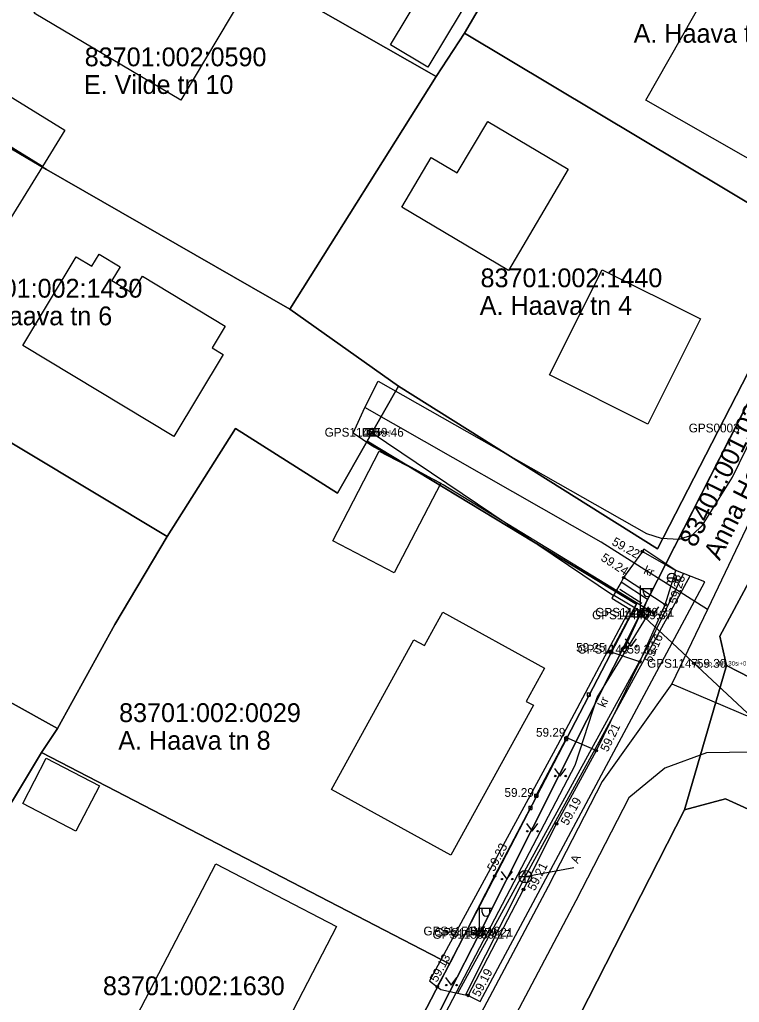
# Model space of a CAD drawing. Extents: x 580119 to 583377, y 6518915 to 6520820.
# Drawn here: x 581802.2 to 581859.6, y 6520069.8 to 6520148.1 of the extents above; entities that cross this region are included whole.
import ezdxf

# ---------------------------------------------------------------- set-up
doc = ezdxf.new("R2010")
doc.units = 0
for name, color, linetype in [('AED', 7, 'Continuous'), ('ELRAJATISMP', 7, 'Continuous'), ('HALJASTUS', 7, 'Continuous'), ('Hoone Elu- või ühiskondlik hoone', 7, 'Continuous'), ('Hoone Kõrval- või tootmishoone', 7, 'Continuous'), ('Hoone Vundament', 7, 'Continuous'), ('KKAEV', 7, 'Continuous'), ('KORGUS-EH2000', 7, 'Continuous'), ('KTRASS', 7, 'Continuous'), ('L_AADRESS', 7, 'Continuous'), ('MAAMUDEL', 7, 'Continuous'), ('MOOTKORG-EH2000', 7, 'Continuous'), ('MOOTMPUNKT', 7, 'Continuous'), ('MOOTNR', 7, 'Continuous'), ('MOOTPIIR', 7, 'Continuous'), ('MPOHULIIN', 7, 'Continuous'), ('PIIR', 7, 'Continuous'), ('POST', 7, 'Continuous'), ('Rippe kõrgus', 7, 'Continuous'), ('SIOHULIIN', 7, 'Continuous'), ('TEE', 7, 'Continuous'), ('Tee Liiklusala', 7, 'Continuous'), ('Tee Tänav Kruuskate', 7, 'Continuous'), ('Tee Tänav Püsikate', 7, 'Continuous'), ('TUNNUS', 7, 'Continuous'), ('VKAEV', 7, 'Continuous'), ('VTRASS', 7, 'Continuous')]:
    doc.layers.add(name, color=color, linetype=linetype)

msp = doc.modelspace()

# ---------------------------------------------------------------- linework, layer by layer
at = {"layer": 'AED'}
for p, q in [((581849.358, 6520097.716), (581851.334, 6520101.433)), ((581849.233, 6520097.841), (581849.233, 6520097.591)), ((581849.233, 6520097.841), (581849.483, 6520097.841)), ((581849.233, 6520097.591), (581849.483, 6520097.591)), ((581849.483, 6520097.841), (581849.483, 6520097.591)), ((581847.447, 6520094.431), (581847.447, 6520094.181)), ((581847.447, 6520094.431), (581847.697, 6520094.431)), ((581847.447, 6520094.181), (581847.697, 6520094.181)), ((581847.697, 6520094.431), (581847.697, 6520094.181)), ((581843.392, 6520086.248), (581845.776, 6520090.772)), ((581845.651, 6520090.897), (581845.651, 6520090.647)), ((581845.651, 6520090.897), (581845.901, 6520090.897)), ((581845.651, 6520090.647), (581845.901, 6520090.647)), ((581845.901, 6520090.897), (581845.901, 6520090.647)), ((581843.267, 6520086.373), (581843.267, 6520086.123)), ((581843.267, 6520086.373), (581843.517, 6520086.373)), ((581843.517, 6520086.373), (581843.517, 6520086.123)), ((581843.267, 6520086.123), (581843.517, 6520086.123)), ((581842.798, 6520085.401), (581842.798, 6520085.151)), ((581842.798, 6520085.401), (581843.048, 6520085.401)), ((581842.798, 6520085.151), (581843.048, 6520085.151)), ((581843.048, 6520085.401), (581843.048, 6520085.151))]:
    msp.add_line(p, q, dxfattribs=at)
msp.add_lwpolyline([(581835.497, 6520071.002), (581836.568, 6520072.987), (581840.076, 6520079.831), (581842.923, 6520085.276)], dxfattribs=at)
at = {"layer": 'ELRAJATISMP'}
for p, q in [((581830.086, 6520115.519), (581830.086, 6520114.922)), ((581830.358, 6520115.519), (581830.358, 6520114.922)), ((581851.586, 6520101.061), (581851.586, 6520100.464)), ((581851.857, 6520101.061), (581851.857, 6520100.464))]:
    msp.add_line(p, q, dxfattribs=at)
for points in [[(581829.625, 6520115.519), (581830.819, 6520115.519), (581830.819, 6520114.922), (581829.625, 6520114.922)], [(581851.124, 6520101.061), (581852.319, 6520101.061), (581852.319, 6520100.464), (581851.124, 6520100.464)]]:
    msp.add_lwpolyline(points, close=True, dxfattribs=at)
at = {"layer": 'HALJASTUS'}
for p, q in [((581851.818, 6520101.572), (581850.061, 6520102.69)), ((581852.272, 6520101.297), (581852.735, 6520100.69)), ((581852.735, 6520100.69), (581853.181, 6520101.297)), ((581850.491, 6520098.745), (581850.954, 6520098.138)), ((581850.954, 6520098.138), (581851.4, 6520098.745)), ((581844.852, 6520088.418), (581845.315, 6520087.811)), ((581845.315, 6520087.811), (581845.761, 6520088.418)), ((581842.616, 6520084.013), (581843.08, 6520083.406)), ((581843.08, 6520083.406), (581843.525, 6520084.013)), ((581840.59, 6520080.203), (581841.054, 6520079.596)), ((581841.054, 6520079.596), (581841.499, 6520080.203)), ((581838.39, 6520075.799), (581838.853, 6520075.192)), ((581838.853, 6520075.192), (581839.299, 6520075.799)), ((581836.154, 6520071.744), (581836.618, 6520071.137)), ((581836.618, 6520071.137), (581837.063, 6520071.744))]:
    msp.add_line(p, q, dxfattribs=at)
msp.add_lwpolyline([(581849.642, 6520102.211), (581851.868, 6520100.864), (581852.266, 6520101.891), (581850.159, 6520103.272)], dxfattribs=at)
for centre in [(581852.334, 6520100.69), (581853.163, 6520100.69), (581850.553, 6520098.138), (581851.382, 6520098.138), (581844.914, 6520087.811), (581845.743, 6520087.811), (581842.679, 6520083.406), (581843.507, 6520083.406), (581840.653, 6520079.596), (581841.481, 6520079.596), (581838.452, 6520075.192), (581839.281, 6520075.192), (581836.217, 6520071.137), (581837.045, 6520071.137)]:
    msp.add_circle(centre, 0.055, dxfattribs=at)
at = {"layer": 'Hoone Elu- või ühiskondlik hoone'}
for points in [[(581820.033, 6520150.116), (581815.051, 6520141.712), (581803.344, 6520148.653), (581808.326, 6520157.057)], [(581852.13, 6520141.691), (581859.68, 6520154.991), (581868.781, 6520149.822), (581865.61, 6520144.241), (581867.15, 6520143.372), (581862.77, 6520135.652)], [(581808.51, 6520129.427), (581810.185, 6520128.419), (581809.526, 6520127.321), (581811.166, 6520126.336), (581811.973, 6520127.674), (581818.588, 6520123.693), (581817.547, 6520121.957), (581818.418, 6520121.435), (581814.469, 6520114.888), (581802.432, 6520122.134), (581806.694, 6520129.217), (581807.935, 6520128.473)], [(581856.487, 6520124.265), (581852.294, 6520115.878), (581844.456, 6520119.798), (581848.65, 6520128.184)], [(581843.178, 6520093.45), (581836.591, 6520081.493), (581827.059, 6520086.744), (581833.636, 6520098.683), (581834.479, 6520098.219), (581835.94, 6520100.872), (581844.04, 6520096.41), (581842.578, 6520093.757)], [(581825.267, 6520068.487), (581821.358, 6520060.968), (581810.468, 6520066.639), (581817.832, 6520080.816), (581827.456, 6520075.811), (581824.001, 6520069.151)]]:
    msp.add_lwpolyline(points, close=True, dxfattribs=at)
at = {"layer": 'Hoone Kõrval- või tootmishoone'}
for points in [[(581837.404, 6520148.761), (581834.753, 6520144.334), (581831.776, 6520146.116), (581834.427, 6520150.544)], [(581803.994, 6520136.423), (581796.95, 6520140.751), (581798.728, 6520143.644), (581805.772, 6520139.316)], [(581796.95, 6520140.751), (581803.994, 6520136.423), (581800.922, 6520131.425), (581795.455, 6520134.786), (581794.09, 6520132.566), (581789.097, 6520135.635), (581792.803, 6520141.666), (581796.221, 6520139.565)], [(581832.67, 6520133.172), (581835.02, 6520137.132), (581837.09, 6520135.912), (581839.52, 6520140.002), (581845.95, 6520136.191), (581841.17, 6520128.132)], [(581804.301, 6520089.226), (581808.544, 6520087.024), (581806.669, 6520083.412), (581802.426, 6520085.614)]]:
    msp.add_lwpolyline(points, close=True, dxfattribs=at)
at = {"layer": 'Hoone Vundament'}
msp.add_lwpolyline([(581830.867, 6520113.723), (581835.778, 6520111.172), (581832.066, 6520104.025), (581827.155, 6520106.576)], close=True, dxfattribs=at)
at = {"layer": 'KKAEV'}
for p, q in [((581842.519, 6520079.285), (581842.519, 6520080.285)), ((581842.019, 6520079.785), (581843.019, 6520079.785))]:
    msp.add_line(p, q, dxfattribs=at)
msp.add_circle((581842.519, 6520079.785), 0.5, dxfattribs=at)
at = {"layer": 'KORGUS-EH2000'}
for centre in [(581851.862, 6520105.711), (581850.367, 6520103.628), (581853.692, 6520101.469), (581849.218, 6520097.728), (581851.671, 6520096.92), (581845.807, 6520090.875), (581848.191, 6520089.836), (581843.392, 6520086.248), (581845.018, 6520084.001), (581840.076, 6520079.831), (581842.377, 6520078.763), (581835.497, 6520071.002), (581837.958, 6520070.314)]:
    msp.add_circle(centre, 0.1, dxfattribs=at)
at = {"layer": 'KTRASS'}
msp.add_line((581842.519, 6520079.785), (581846.392, 6520080.516), dxfattribs=at)
msp.add_lwpolyline([(581855.638, 6520103.758), (581842.519, 6520079.785), (581837.745, 6520070.359)], dxfattribs=at)
at = {"layer": 'MOOTMPUNKT'}
for centre in [(581830.222, 6520115.22), (581859.481, 6520115.561), (581855.953, 6520096.795)]:
    msp.add_circle(centre, 0.1, dxfattribs=at)
at = {"layer": 'MOOTPIIR'}
msp.add_lwpolyline([(581834.886, 6520071.472), (581835.497, 6520071.002), (581835.795, 6520070.775), (581837.958, 6520070.314), (581838.912, 6520069.817), (581856.835, 6520103.284), (581854.528, 6520104.199), (581851.988, 6520105.899), (581851.862, 6520105.711), (581850.367, 6520103.628), (581850.159, 6520103.272), (581849.433, 6520101.984), (581850.871, 6520101.105), (581845.086, 6520090.262)], close=True, dxfattribs=at)
at = {"layer": 'MPOHULIIN'}
for p, q in [((581864.425, 6520125.702), (581853.741, 6520104.726)), ((581830.222, 6520115.22), (581849.563, 6520102.214)), ((581853.741, 6520104.726), (581851.721, 6520100.762)), ((581837.895, 6520075.45), (581838.86, 6520075.263))]:
    msp.add_line(p, q, dxfattribs=at)
for points in [[(581851.721, 6520100.762), (581838.86, 6520075.263), (581836.498, 6520070.625)], [(581851.721, 6520100.762), (581854.232, 6520098.424)], [(581854.232, 6520098.424), (581869.033, 6520084.64), (581898.232, 6520068.443), (581929.764, 6520051.169), (581964.377, 6520031.774), (581989.598, 6520017.96), (582014.996, 6520004.053), (582041.548, 6519986.36), (582056.944, 6519974.839)], [(581836.498, 6520070.625), (581821.164, 6520040.517)]]:
    msp.add_lwpolyline(points, dxfattribs=at)
at = {"layer": 'PIIR'}
for points in [[(581818.25, 6520012.64), (581808.31, 6520018.92), (581824.83, 6520050.4), (581836.47, 6520072.82), (581851.4, 6520101.52), (581829.9, 6520114.5), (581832.4, 6520118.89), (581853.07, 6520105.93), (581865.62, 6520130.32), (581875.62, 6520150.43), (581897.71, 6520194.09), (581905.22, 6520189.53), (581889.06, 6520159.5), (581879.18, 6520139.97), (581876.38, 6520134.67), (581873.75, 6520129.28), (581870.97, 6520123.99), (581868.38, 6520118.69), (581865.54, 6520113.3), (581862.86, 6520107.92), (581858.03, 6520098.95), (581858.58, 6520096.63), (581855.23, 6520085.11)], [(581812.15, 6520182.64), (581846.68, 6520162.43), (581837.68, 6520147.06), (581835.4, 6520143.6), (581800.99, 6520163.2)], [(581846.68, 6520162.43), (581848.92, 6520166.07), (581875.62, 6520150.43), (581865.62, 6520130.32), (581837.68, 6520147.06)], [(581790.11, 6520144.42), (581800.99, 6520163.2), (581835.4, 6520143.6), (581823.73, 6520125.03), (581804.32, 6520136.18), (581798.27, 6520139.74)], [(581823.73, 6520125.03), (581835.4, 6520143.6), (581837.68, 6520147.06), (581865.62, 6520130.32), (581853.07, 6520105.93), (581832.4, 6520118.89)], [(581790.11, 6520144.42), (581798.27, 6520139.74), (581804.32, 6520136.18), (581823.73, 6520125.03), (581832.4, 6520118.89), (581829.9, 6520114.5), (581827.55, 6520110.37), (581819.41, 6520115.52), (581813.96, 6520106.91), (581779.28, 6520127.73)], [(581779.28, 6520127.73), (581813.96, 6520106.91), (581809.78, 6520099.89), (581805.2, 6520091.6), (581786.76, 6520101.83), (581782.86, 6520103.86), (581769.84, 6520111.32)], [(581819.41, 6520115.52), (581827.55, 6520110.37), (581829.9, 6520114.5), (581851.4, 6520101.52), (581836.47, 6520072.82), (581803.92, 6520089.68), (581805.2, 6520091.6), (581809.78, 6520099.89), (581813.96, 6520106.91)], [(581768.1, 6520101.82), (581765.39, 6520103.31), (581769.84, 6520111.32), (581782.86, 6520103.86), (581786.76, 6520101.83), (581805.2, 6520091.6), (581803.92, 6520089.68), (581794.38, 6520073.84), (581789.29, 6520076.96), (581762.75, 6520093.2)], [(581858.58, 6520096.63), (581858.03, 6520098.95), (581862.86, 6520107.92), (581873.01, 6520102.73), (581883.66, 6520097.35), (581908.93, 6520084.35), (581904.4, 6520076.28), (581886.27, 6520086), (581879.26, 6520086)], [(581792.34, 6520070.46), (581794.38, 6520073.84), (581803.92, 6520089.68), (581836.47, 6520072.82), (581824.83, 6520050.4), (581803.43, 6520063.65)], [(581888.28, 6520072.43), (581876.44, 6520050.07), (581847.29, 6519995.61), (581818.25, 6520012.64), (581855.23, 6520085.11), (581858.5, 6520085.99)]]:
    msp.add_lwpolyline(points, close=True, dxfattribs=at)
msp.add_lwpolyline([(581949.86, 6520009.55), (581943.51, 6520012.98), (581956.4, 6520035.78), (581930.04, 6520050.18), (581888.28, 6520072.43), (581858.5, 6520085.99), (581855.23, 6520085.11), (581858.58, 6520096.63), (581879.26, 6520086), (581886.27, 6520086), (581904.4, 6520076.28), (581908.93, 6520084.35), (581911.76, 6520089.61), (581914.75, 6520094.85), (581917.61, 6520100.1), (581919.2, 6520103.01), (581923.71, 6520100.64), (581925.66, 6520099.62), (581920.7, 6520095.82), (581908.98, 6520073.94), (581935.27, 6520059.68), (581961.38, 6520044.71)], dxfattribs=at)
at = {"layer": 'POST'}
for p, q in [((581851.721, 6520101.012), (581851.721, 6520103.012)), ((581851.721, 6520102.762), (581852.721, 6520102.762)), ((581851.948, 6520102.441), (581851.948, 6520102.762)), ((581852.561, 6520102.441), (581852.561, 6520102.762)), ((581851.721, 6520100.762), (581851.721, 6520100.762)), ((581838.86, 6520075.513), (581838.86, 6520077.513)), ((581838.86, 6520077.263), (581839.86, 6520077.263)), ((581839.087, 6520076.942), (581839.087, 6520077.263)), ((581839.7, 6520076.942), (581839.7, 6520077.263)), ((581838.86, 6520075.263), (581838.86, 6520075.263))]:
    msp.add_line(p, q, dxfattribs=at)
msp.add_lwpolyline([(581851.721, 6520100.762), (581850.402, 6520097.925)], dxfattribs=at)
for centre, radius in [((581830.222, 6520115.22), 0.25), ((581851.721, 6520100.762), 0.25), ((581850.402, 6520097.925), 0.2), ((581838.86, 6520075.263), 0.25)]:
    msp.add_circle(centre, radius, dxfattribs=at)
for centre in [(581852.255, 6520102.441), (581839.393, 6520076.942)]:
    msp.add_arc(centre, 0.306, 180, 0, dxfattribs=at)
at = {"layer": 'SIOHULIIN'}
for points in [[(581853.741, 6520104.726), (581864.425, 6520125.702)], [(581854.232, 6520098.424), (581851.721, 6520100.762), (581853.741, 6520104.726)], [(581836.498, 6520070.625), (581838.86, 6520075.263), (581851.721, 6520100.762)], [(581869.033, 6520084.64), (581854.232, 6520098.424)], [(581808.669, 6520016.764), (581821.164, 6520040.517), (581836.498, 6520070.625)]]:
    msp.add_lwpolyline(points, dxfattribs=at)
at = {"layer": 'TEE'}
for points in [[(581851.862, 6520105.711), (581854.528, 6520104.199)], [(581837.958, 6520070.314), (581842.377, 6520078.763), (581845.018, 6520084.001), (581848.191, 6520089.836), (581851.671, 6520096.92), (581853.692, 6520101.469), (581854.528, 6520104.199)], [(581853.692, 6520101.469), (581850.367, 6520103.628)], [(581851.671, 6520096.92), (581849.218, 6520097.728)], [(581845.807, 6520090.875), (581848.191, 6520089.836)]]:
    msp.add_lwpolyline(points, dxfattribs=at)
at = {"layer": 'Tee Liiklusala'}
for points in [[(581742.215, 6520054.723), (581805.663, 6520015.653), (581807.918, 6520015.737), (581809.742, 6520016.857), (581827.568, 6520051.921), (581835.83, 6520068.282), (581846.508, 6520088.672), (581848.263, 6520094.065), (581852.483, 6520100.961), (581835.959, 6520111.027), (581830.266, 6520114.149), (581828.794, 6520115.158), (581829.718, 6520117.195), (581830.788, 6520119.284), (581852.184, 6520107.138), (581853.36, 6520106.77), (581854.804, 6520106.704), (581855.859, 6520107.038), (581856.65, 6520107.81), (581859.04, 6520111.64), (581881.29, 6520157.17)], [(581951.622, 6520039.928), (581930.601, 6520052.21), (581908.83, 6520065.921), (581904.459, 6520069.499), (581880.476, 6520080.917), (581860.654, 6520089.709), (581856.965, 6520089.651), (581853.653, 6520088.441), (581850.79, 6520086.066), (581846.566, 6520077.855), (581840.27, 6520065.98), (581832.895, 6520051.299), (581814.422, 6520014.831), (581814.487, 6520011.909), (581816.356, 6520009.507), (581833.173, 6519999.999), (581968.761, 6519918.78)]]:
    msp.add_lwpolyline(points, dxfattribs=at)
at = {"layer": 'Tee Tänav Kruuskate'}
msp.add_lwpolyline([(581857.05, 6520101.082), (581848.58, 6520106.462), (581829.718, 6520117.195)], dxfattribs=at)
at = {"layer": 'Tee Tänav Püsikate'}
for points in [[(581904.384, 6520197.949), (581891.674, 6520171.939), (581884.02, 6520156.581), (581876.34, 6520141.461), (581857.05, 6520101.082)], [(581857.05, 6520101.082), (581854.2, 6520095.172)], [(581854.2, 6520095.172), (581848.649, 6520087.369), (581844.35, 6520079.012), (581838.05, 6520067.131), (581809.38, 6520010.542)], [(581854.2, 6520095.172), (581861.65, 6520092.002), (581881.49, 6520083.202), (581905.64, 6520071.702)]]:
    msp.add_lwpolyline(points, dxfattribs=at)
at = {"layer": 'VKAEV'}
for p, q in [((581853.854, 6520103.627), (581854.554, 6520103.627)), ((581853.957, 6520103.38), (581853.817, 6520103.24)), ((581854.451, 6520103.38), (581854.591, 6520103.24))]:
    msp.add_line(p, q, dxfattribs=at)
msp.add_circle((581854.204, 6520103.627), 0.35, dxfattribs=at)
at = {"layer": 'VTRASS'}
msp.add_line((581854.204, 6520103.627), (581854.832, 6520103.318), dxfattribs=at)
msp.add_lwpolyline([(581837.138, 6520070.489), (581851.933, 6520097.485), (581852.507, 6520098.532), (581855.141, 6520103.956)], dxfattribs=at)

# ---------------------------------------------------------------- texts
at = {"layer": 'KORGUS-EH2000'}
for s, rotation, p in [(' 59.22', 330.44083, (581849.138, 6520106.415)), (' 59.24', 327.00431, (581848.271, 6520105.185)), (' 59.28', 72.96455, (581854.528, 6520101.213)), (' 59.16', 66.05189, (581852.471, 6520096.565)), (' 59.21', 63.83848, (581848.977, 6520089.45)), (' 59.19', 61.45736, (581845.786, 6520083.583)), (' 59.23', 62.40186, (581839.921, 6520079.912)), (' 59.21', 63.24539, (581843.158, 6520078.369)), (' 59.13', 61.65057, (581835.343, 6520071.085)), (' 59.19', 62.3903, (581838.733, 6520069.908))]:
    msp.add_text(s, height=0.7, rotation=rotation, dxfattribs=at).set_placement(p)
for s, p in [(' 59.25', (581846.314, 6520097.715)), (' 59.29', (581843.116, 6520090.944)), (' 59.29', (581840.6, 6520086.146))]:
    msp.add_text(s, height=0.7, dxfattribs=at).set_placement(p)
at = {"layer": 'L_AADRESS'}
for s, p in [('A. Haava tn 4a', (581851.163, 6520146.282)), ('E. Vilde tn 10', (581807.305, 6520142.202)), ('A. Haava tn 4', (581838.888, 6520124.582)), ('A. Haava tn 6', (581797.409, 6520123.752)), ('A. Haava tn 8', (581810.048, 6520089.907))]:
    msp.add_text(s, height=1.5, dxfattribs=at).set_placement(p)
msp.add_text('Anna Haava tänav L2', height=1.5, rotation=63.70997, dxfattribs=at).set_placement((581858.028, 6520104.927))
at = {"layer": 'MAAMUDEL'}
for s in [' kaabel', ' kilp']:
    msp.add_text(s, height=0.35, dxfattribs=at).set_placement((581830.222, 6520115.045))
at = {"layer": 'MOOTKORG-EH2000'}
for s, p in [(' 59.46', (581830.222, 6520114.87)), (' 59.31', (581851.811, 6520100.517)), (' 59.37', (581851.632, 6520100.307)), (' 59.33', (581850.402, 6520097.575)), (' 59.30', (581855.953, 6520096.445)), (' 59.16', (581837.895, 6520075.1)), (' 59.17', (581838.756, 6520074.834)), (' 59.21', (581838.965, 6520074.992))]:
    msp.add_text(s, height=0.7, dxfattribs=at).set_placement(p)
at = {"layer": 'MOOTNR'}
for s, p in [('GPS1148 ', (581826.512, 6520114.87)), ('GPS0003 ', (581855.561, 6520115.211)), ('GPS1145 ', (581848.101, 6520100.517)), ('GPS1144 ', (581847.852, 6520100.307)), ('GPS1146 ', (581846.692, 6520097.575)), ('GPS1147 ', (581852.243, 6520096.445)), ('GPS1151 ', (581834.395, 6520075.1)), ('GPS1150 ', (581835.117, 6520074.834)), ('GPS1149 ', (581835.255, 6520074.992))]:
    msp.add_text(s, height=0.7, dxfattribs=at).set_placement(p)
at = {"layer": 'Rippe kõrgus'}
msp.add_text(' el_mp_ohl5.30si+0.50s+1.65tv+0.35mp', height=0.35, dxfattribs=at).set_placement((581855.953, 6520096.62))
at = {"layer": 'TEE'}
for s, rotation, p in [('kr', 337.63405, (581851.91, 6520103.975)), ('kr', 66.35649, (581848.897, 6520093.219)), ('A', 66.35649, (581846.719, 6520080.778))]:
    msp.add_text(s, height=0.7, rotation=rotation, dxfattribs=at).set_placement(p)
at = {"layer": 'TUNNUS'}
for s, p in [('83701:002:0590', (581807.369, 6520144.407)), ('83701:002:1440', (581838.951, 6520126.787)), ('83701:002:1430', (581797.472, 6520125.957)), ('83701:002:0029', (581810.111, 6520092.112)), ('83701:002:1630', (581808.825, 6520070.332))]:
    msp.add_text(s, height=1.5, dxfattribs=at).set_placement(p)
msp.add_text('83401:001:0219', height=1.5, rotation=63.70997, dxfattribs=at).set_placement((581856.079, 6520105.96))

doc.saveas('drawing.dxf')
